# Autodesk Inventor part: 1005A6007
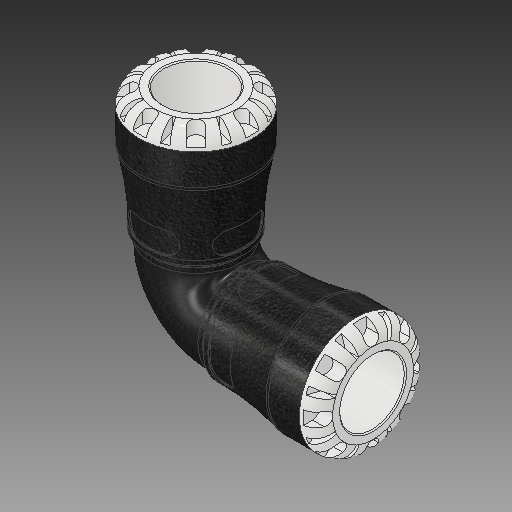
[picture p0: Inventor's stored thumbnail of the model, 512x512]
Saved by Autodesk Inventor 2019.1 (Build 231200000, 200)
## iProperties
Created: 2016-12
Part Number: 1005A6007
Material: PVC-Piping
Description: PLASSON 90° ELBOW 3/4''IPS SERIES 1
Document SubType Name: Modeling
Designer: KIM
Mass: 664.223 g
Surface Area: 733.008 cm^2
Volume: 474.445 cm^3
Density: 1.4 g/cm^3
Appearance: Black Cast
Author: KIM
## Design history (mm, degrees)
derived "1005A.ipt"
feature "Solid1::1005A.ipt"
tag "TaggingFeature1"
body "Solid1"
other parameters: "d1" = 20.16252, "d2" = 26.6, "d3" = 33.25, "d4" = 46.99, "d8" = 39.9415, "d13" = 5.496, "d14" = 5.496, "d15" = 0, "d17" = 360 deg, "d19" = 8 deg, "d20" = 0.532, "d21" = 0.532, "d22" = 8 deg, "d24" = 0, "d26" = 360 deg, "d33" = 4.699, "d43" = 36.6522, "d51" = 0.4699, "d54" = 9.31, "d55" = 5.852, "d57" = 10.77216, "d58" = 0, "d74" = 0, "d77" = 2.21667, "d78" = 48.006, "d82" = 0.532, "d115" = 360 deg, "d207" = 90 deg, "d228" = 7.9135, "d247" = 0.9398, "d248" = 2.88036, "d268" = 21.96783, "d269" = 2.88036, "d270" = 72.898, "d272" = 90 deg, "d274" = 0, "d275" = 0, "d_" = 26.6, "E_" = 46.99, "l_" = 48.006, "A_" = 72.898, "d9" = 6.87, "d11" = 46.99, "d12" = 33.25
